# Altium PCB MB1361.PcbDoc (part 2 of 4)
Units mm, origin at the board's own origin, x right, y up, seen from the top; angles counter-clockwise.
Board outline 70 x 133.34 mm, 6 copper layers (Top Layer, Signal Layer 1, Signal Layer 2, Signal Layer 3, Signal Layer 4, Bottom Layer), stack 1.578 mm thick; 268 components, 251 nets, 1066 pads, 705 vias.
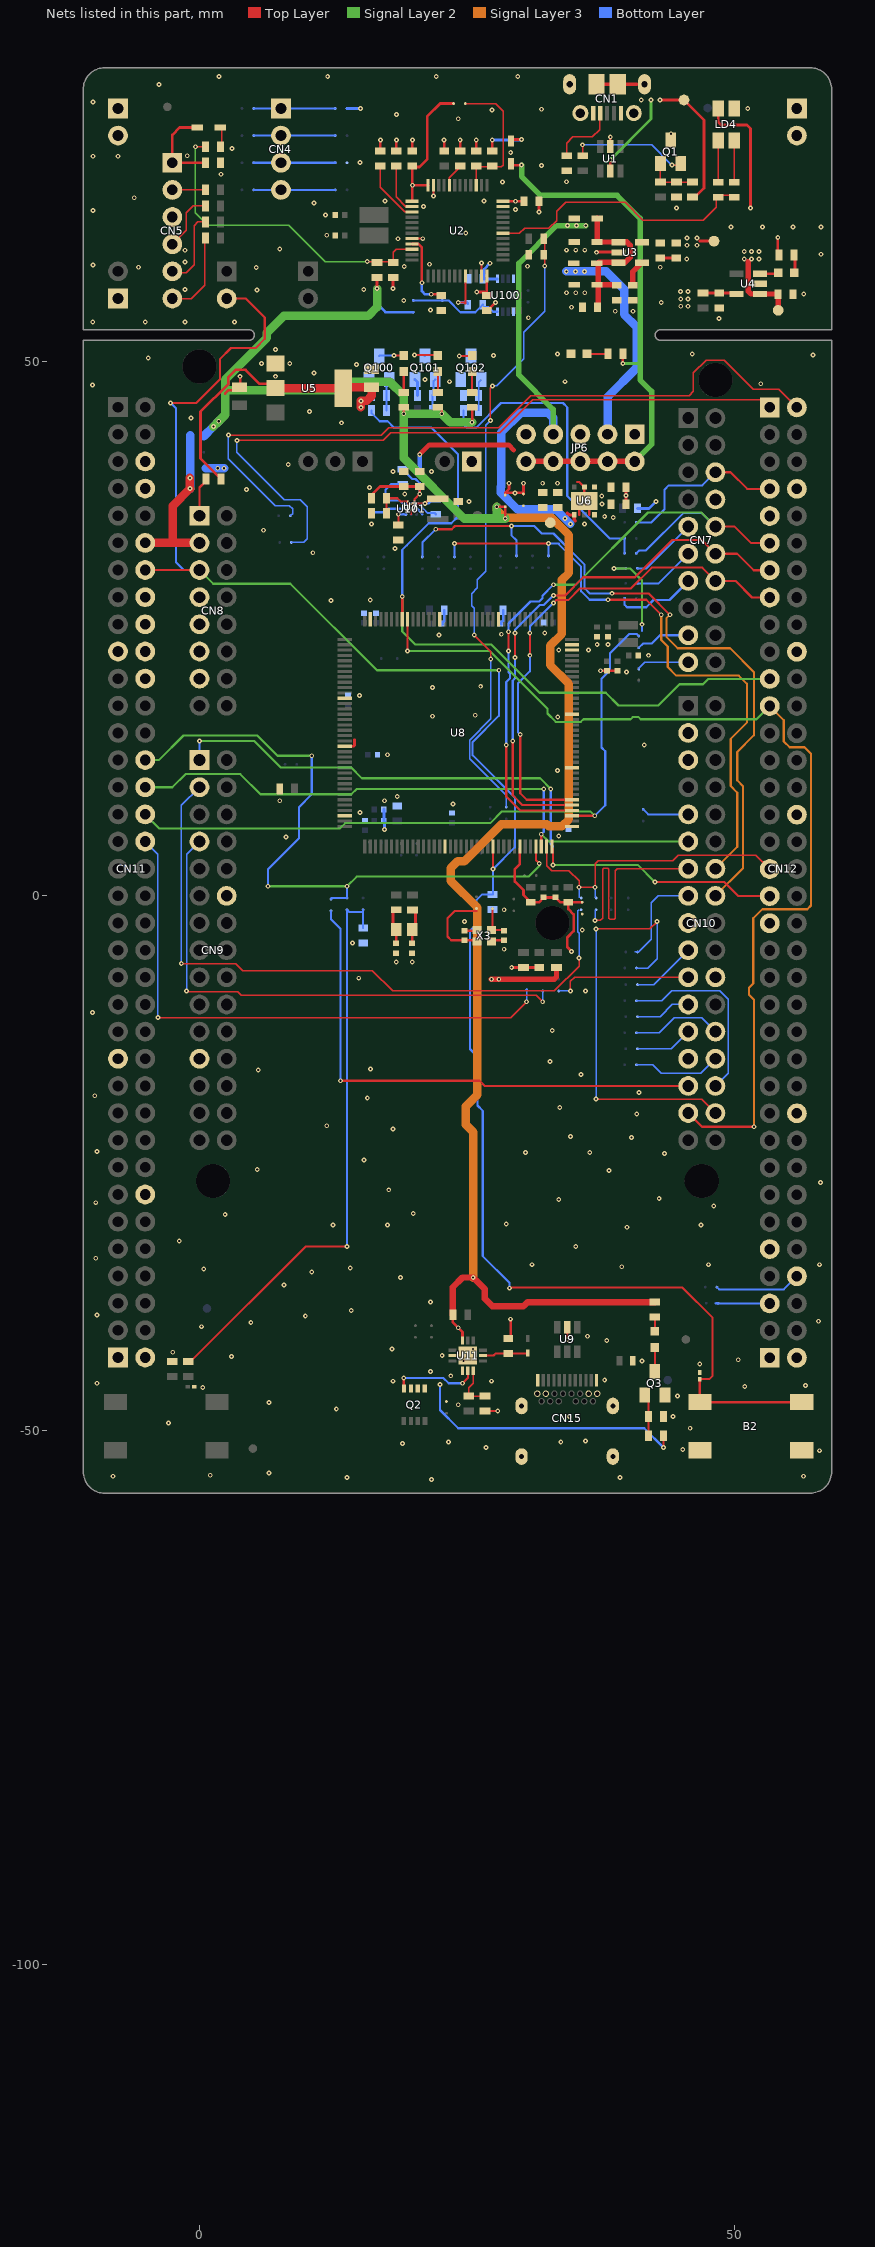
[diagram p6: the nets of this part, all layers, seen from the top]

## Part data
B1: library part MCD-00002, "Non-Open Push-Button 0.1A 24V BLUE", Manufacturer=WEALTHMETAL, Manufacturer_Part_Number=TD0341X-G01-BLU
B2: library part MCD-00001, "Non-Open Push-Button 0.1A 24V BLACK", Manufacturer=WEALTHMETAL, Manufacturer_Part_Number=TD0341X-G01-BLA
C1 C2 C3 C6 C11 C13 C14 C15 C18 C21 C24 C100 C101 C102 C120 C121: library part MCD-00211, "Capacitor, MLCC, 100nF, 16V, X7R, 10%, 0603, T=0,8mm", Manufacturer=YAGEO, Manufacturer_Part_Number=CC0603KRX7R7BB104, Package=C0603
C4 C5: library part MCD-00015, "Capacitor, MLCC, 10pF, 50V, NPO, 5%, 0402, T=0,5mm", Manufacturer=YAGEO, Manufacturer_Part_Number=CC0402JRNPO9BN100, Package=C0402
C7 C9 C12 C20 C22 C30 C31 C114: library part MCD-00010, "Capacitor, MLCC, 1uF, 16V, X5R, 10%, 0603, T=0,8mm", Manufacturer=YAGEO, Manufacturer_Part_Number=CC0603KRX5R7BB105, Package=C0603
C8: library part MCD-00638, "Capacitor, MLCC, 20pF, 50V, NPO, 5%, 0603, T=0,8mm", Manufacturer=YAGEO, Manufacturer_Part_Number=CC0603JRNPO9BN200, Package=C0603
C10: library part MCD-00017, "Capacitor, MLCC, 10nF, 50V, X7R, 10%, 0603, T=0.8mm", Manufacturer=YAGEO, Manufacturer_Part_Number=CC0603KRX7R9BB103, Package=C0603
C16 C17: library part MCD-00014, "Capacitor, MLCC, 10uF, 25V, X5R, 10%, 0805, T=0,85mm", Manufacturer=YAGEO, Manufacturer_Part_Number=CC0805KRX5R8BB106, Package=C0805
C19 C23: library part MCD-00243, "Capacitor, MLCC, 10uF, 6V3, X5R, 10%, 0603, T=0,8mm", Manufacturer=YAGEO, Manufacturer_Part_Number=CC0603KRX5R5BB106, Package=C0603
C25 C32 C33 C105 C106 C107 C108 C109 C110 C111 C112 C113 C116 C117 C118 C119: library part MCD-00102, "Capacitor, MLCC, 100nF, 16V, X7R, 10%, 0402, T=0,5mm", Alternate_Manufacturer=MURATA, Alternate_Manufacturer_Part_Number=GCM155R71C104KA55D, Manufacturer=YAGEO, Manufacturer_Part_Number=CC0402KRX7R7BB104, Package=C0402
C26 C115: library part MCD-01356, "Capacitor, MLCC, 4.7uF, 6V3, X5R, 20%, 0402, T=0,5mm", Manufacturer=MURATA, Manufacturer_Part_Number=GRM155R60J475ME47, Package=C0402
C27: library part MCD-00205, "Capacitor, MLCC, 100pF, 50V, NPO, 5%, 0402, T=0,5mm", Manufacturer=YAGEO, Manufacturer_Part_Number=CC0402JRNPO9BN101, Package=C0402
C28 C29: library part MCD-01355, "Capacitor, MLCC, 10uF, 4V, X5R, 20%, 0402, T=0,5mm", Manufacturer=MURATA, Manufacturer_Part_Number=GRM155R60G106ME44, Package=C0402
C34 C35: library part MCD-00674, "Capacitor, MLCC, 6.8pF, 50V, NPO, +-0.25pF, 0402, T=0.5mm", Manufacturer=YAGEO, Manufacturer_Part_Number=CC0402CRNPO9BN6R8, Package=C0402
C36 C37: library part MCD-00556, "Capacitor, MLCC, 3.9pF, 50V, NPO, +-0.25pF, 0402, T=0,5mm", Manufacturer=YAGEO, Manufacturer_Part_Number=CC0402CRNPO9BN3R9, Package=C0402
C38: library part MCD-00637, "Capacitor, MLCC, 10pF, 50V, NPO, 5%, 0603, T=0,8mm", Manufacturer=YAGEO, Manufacturer_Part_Number=CC0603JRNPO9BN100, Package=C0603
C40: library part MCD-01099, "Capacitor,100nF,50V,X7R,10%,0603", Manufacturer=YAGEO, Manufacturer_Part_Number=CC0603KRX7R9BB104, Package=C0603
C103 C104: library part MCD-01121, "Capacitor, MLCC, 4.7µF, 10V, X5R, 20%, 0603, T=0,8mm", Manufacturer=MURATA, Manufacturer_Part_Number=GRM188R61A475ME15, Package=C0603
CN1: library part MCD-00028, "USB-MICRO-B, 0.65mm, RA, SMT, Bottom Mount,", Manufacturer=MOLEX, Manufacturer_Part_Number=1050170001
CN2 CN3 CN13 CN14: library part MCD-00214, "Header, 2x1, 2,54mm, VR, TH, Height 5.84mm/10.16mm", Manufacturer=SAMTEC, Manufacturer_Part_Number=TSW-102-09-x-S
CN4: library part MCD-00029, "Header, 4x1, 2,54mm, VR, TH, Height 5.84mm/2.54mm", Manufacturer=SAMTEC, Manufacturer_Part_Number=TSW-104-07-x-S
CN5: library part MCD-00212, "Header, 6x1, 2,54mm, VR, TH, Height 5.84mm/2.54mm", Manufacturer=SAMTEC, Manufacturer_Part_Number=TSW-106-07-x-S
CN6: library part MCD-00032, "Header, 2x1, 2,54mm, VR, TH, Height 5.84mm/2.54mm", Manufacturer=SAMTEC, Manufacturer_Part_Number=TSW-102-07-x-S
CN7: library part MCD-01039, "Socket, 10x2, 2.54mm, VR, TH, Height 8.51mm/10mm, Low insertion force.", Manufacturer=SAMTEC, Manufacturer_Part_Number=SSW-110-23-x-D
CN8: library part MCD-01037, "Socket, 8x2, 2.54mm, VR, TH, Height 8.51mm/10mm, Low insertion force.", Manufacturer=SAMTEC, Manufacturer_Part_Number=SSW-108-23-x-D
CN9: library part MCD-01040, "Socket, 15x2, 2.54mm, VR, TH, Height 8.51mm/10mm, Low insertion force.", Manufacturer=SAMTEC, Manufacturer_Part_Number=SSW-115-23-x-D
CN10: library part MCD-01041, "Socket, 17x2, 2.54mm, VR, TH, Height 8.51mm/10mm, Low insertion force", Manufacturer=SAMTEC, Manufacturer_Part_Number=SSW-117-23-x-D
CN11 CN12: library part MCD-01210, "Header, 35x2, 2,54mm, VR, TH, Height 5.84mm/2.54mm", Manufacturer=SAMTEC, Manufacturer_Part_Number=TSW-135-07-x-D
CN15: library part MCD-01108, "USB tyce C certified receptacle for 1.6mm pcb height", Manufacturer="CHANT SINCERE (COXOC)", Manufacturer_Part_Number=317JD24BZTF3K3C3
D1 D2 D3 D4 D5 D6: library part MCD-00034, "BAT60JFILM", Manufacturer=STMICROELECTRONICS
D7: library part MCD-01677, "Small signal Schottky diodes", Manufacturer=STMICROELECTRONICS, Manufacturer_Part_Number=BAT54KFILM, Package=SOD-523
HW101: library part MCD-00235, "Sticker to mention board reference + serial number", Manufacturer=n/a
HW102: library part MCD-00547, "Sticker to mention board CPN code", Manufacturer=n/a
JP2: library part MCD-00045, "Header, 2x1, 2,54mm, VR, TH, Height 5.84mm/2.54mm", Manufacturer=SAMTEC, Manufacturer_Part_Number=TSW-102-07-x-S
JP3 JP5: library part MCD-00683, "Header, 2x1, 2,54mm, VR, TH, Height 5.84mm/2.54mm - Shunt Fitted by default", Manufacturer=SAMTEC, Manufacturer_Part_Number=TSW-102-07-x-S
JP4: library part MCD-00684, "Header, 3x1, 2,54mm, VR, TH, Height 5.84mm/2.54mm - Shunt Fitted 1-2 by default", Manufacturer=SAMTEC, Manufacturer_Part_Number=TSW-103-07-F-S
JP6: library part MCD-01203, "Header, 5x2, 2,54mm, VR, TH, Height 5.84mm/2.54mm - Shunt Fitted 1-2", Manufacturer=SAMTEC, Manufacturer_Part_Number=TSW-105-07-x-D
L1: library part MCD-00240, "FIXED IND 2.2UH 2.6A 100 mOHM 20% SMD", Manufacturer=TDK, Manufacturer_Part_Number=VLS252010HBX-2R2M-1
L2: library part MCD-01786, "Power Inductor 4.7uH 1.1A 160 mOHM 20% SMD Multilayer ferrite.", Manufacturer=TDK, Manufacturer_Part_Number=MLP2016H4R7MT0S1, Package=L0806
LD1 LD6 LD7: library part MCD-00050, "LED, Green, 0603", Manufacturer=EVERLIGHT, Manufacturer_Part_Number=19-213SYGC/S530-E2/TR8, Package="LED 0603"
LD2: library part MCD-00584, "LED Blue, 0603 SMD, 3.3 V Forward Voltage", Manufacturer=VISHAY, Manufacturer_Part_Number=VLMB1300-GS08, Package="LED 0603"
LD3 LD5: library part MCD-00322, "LED, Red, 0603", Manufacturer=EVERLIGHT, Manufacturer_Part_Number=19-217/R6C-AL1M2VY/3T, Package="LED 0603"
LD4: library part MCD-00051, "LED Bicolor", Alternate_Manufacturer=EVERLUCK, Alternate_Manufacturer_Part_Number=LE-RGW35280, Manufacturer="AVAGO TECHNOLOGIES", Manufacturer_Part_Number=HSMF-A201-A00J1
Q1 Q3 Q100 Q101 Q102: library part MCD-00073, "NPN Bipolar Transistor", Manufacturer=NXP, Manufacturer_Part_Number=BSR14
Q2: library part MCD-01810, "N-channel 30 V, 6 mO typ, 11 A STripFET™ H6, Power MOSFET in a PowerFLAT™ 3.3x3.3 package", Manufacturer=STMICROELECTRONICS, Package="PowerFLAT 3.3x3.3"
R1 R10 R19 R24: library part MCD-00224, "Resistor,100R,0603,1%,1/10W", Manufacturer=YAGEO, Manufacturer_Part_Number=RC0603FR-07100RL, Package=R0603
R2 R3 R9 R12 R23 R33 R43 R44: library part MCD-00220, "Resistor,10K,0603,1%,1/10W", Manufacturer=YAGEO, Manufacturer_Part_Number=RC0603FR-0710KL, Package=R0603
R4 R7 R39 R104 R106 R108: library part MCD-00223, "Resistor,100K,0603,1%,1/10W", Manufacturer=YAGEO, Manufacturer_Part_Number=RC0603FR-07100KL, Package=R0603
R5 R21 R22: library part MCD-00219, "Resistor,4K7,0603,1%,1/10W", Manufacturer=YAGEO, Manufacturer_Part_Number=RC0603FR-074K7L, Package=R0603
R6 R45: library part MCD-00218, "Resistor,2K7,0603,1%,1/10W", Manufacturer=YAGEO, Manufacturer_Part_Number=RC0603FR-072K7L, Package=R0603
R8: library part MCD-00217, "Resistor,1K5,0603,1%,1/10W", Manufacturer=YAGEO, Manufacturer_Part_Number=RC0603FR-071K5L, Package=R0603
R11: library part MCD-00221, "Resistor,36K,0603,1%,1/10W", Manufacturer=YAGEO, Manufacturer_Part_Number=RC0603FR-0736KL, Package=R0603
R13 R14 R40: library part MCD-00197, "Resistor,330R,0603,1%,1/10W", Manufacturer=YAGEO, Manufacturer_Part_Number=RC0603FR-07330RL, Package=R0603
R15 R16 R17 R18: library part MCD-00190, "Resistor,22R,0603,1%,1/10W", Manufacturer=YAGEO, Manufacturer_Part_Number=RC0603FR-0722RL, Package=R0603
R20 R25 R28 R31: library part MCD-00070, "Resistor,1K,0603,1%,1/10W", Manufacturer=YAGEO, Manufacturer_Part_Number=RC0603FR-071KL, Package=R0603
R29: library part MCD-00508, "Resistor,680R,0603,1%,1/10W", Manufacturer=YAGEO, Manufacturer_Part_Number=RC0603FR-07680RL, Package=R0603
R30 R38: library part MCD-00225, "Resistor,510R,0603,1%,1/10W", Manufacturer=YAGEO, Manufacturer_Part_Number=RC0603FR-07510RL, Package=R0603
R32: library part MCD-00242, "Resistor,19K6,0603,1%,1/10W", Manufacturer=YAGEO, Manufacturer_Part_Number=RC0603FR-0719K6L, Package=R0603
R34 R35 R100 R101 R102 R103: library part MCD-00056, "Resistor,0R,0603,5%,1/10W", Manufacturer=YAGEO, Manufacturer_Part_Number=RC0603JR-070RL, Package=R0603
R36: library part MCD-01171, "Resistor,49K9,0603,1%", Manufacturer=YAGEO, Manufacturer_Part_Number=RC0603FR-0749K9L, Package=R0603
R37: library part MCD-00458, "Resistor,330K,0603,1%,1/10W", Manufacturer=YAGEO, Manufacturer_Part_Number=RC0603FR-07330KL, Package=R0603
R41: library part MCD-00430, "Resistor,22K,0603,1%,1/10W", Manufacturer=YAGEO, Manufacturer_Part_Number=RC0603FR-0722KL, Package=R0603
R42 R105 R107 R109: library part MCD-00222, "Resistor,47K,0603,1%,1/10W", Manufacturer=YAGEO, Manufacturer_Part_Number=RC0603FR-0747KL, Package=R0603
SB1 SB2 SB3 SB4 SB5 SB6 SB7 SB8 SB9 SB10 SB11 SB12 SB100 SB101 SB102 SB103 SB104 SB105 SB106 SB107 SB108 SB109 SB110 SB111 SB112 SB113 SB114 SB115 SB116 SB117 SB118 SB119 SB120 SB121 SB122 SB123 SB124 SB125 SB126 SB127 SB128 SB129 SB130 SB132 SB133 SB134 SB135 SB136 SB137 SB138 SB139 SB140 SB142 SB143 SB144 SB145 SB146 SB147 SB148 SB149 SB150 SB151 SB152 SB153 SB154 SB155 SB156 SB157 SB158 SB159 SB160 SB161 SB162 SB163 SB164 SB165 SB166 SB167 SB168: library part MCD-00071, "Solder Bridge ON"
TP1 TP2 TP3 TP4 TP5: library part MCD-00074, "Test Point 1mm", Manufacturer=n/a
U1: library part MCD-00163, "Very low capacitance ESD protection", Manufacturer=STMICROELECTRONICS, Manufacturer_Part_Number=USBLC6-2SC6
U2: library part MCD-00085, "Medium-density performance line ARM-based 32-bit MCU with 128KB Flash", Manufacturer=STMICROELECTRONICS, Manufacturer_Part_Number=STM32F103CBT6
U3: library part MCD-00086, "Ultra low drop-low noise BiCMOS voltage, regulators low ESR capacitors compatible", Manufacturer=STMICROELECTRONICS, Manufacturer_Part_Number=LD3985M33R
U4: library part MCD-01785, "5V Power Switch, 0.85A, RDSon 130mOhm max, with active low enable pin", Manufacturer="TEXAS INSTRUMENTS", Manufacturer_Part_Number=TPS2041CDBVT, Package=SOT23_5p
U5: library part MCD-00088, "IC REG LDO 5V 0.8A SOT223", Manufacturer=STMICROELECTRONICS, Manufacturer_Part_Number=LD1117S50TR, Package=SOT-223
U6: library part MCD-00215, "Low quiescent current and low noise voltage regulators", Manufacturer=STMICROELECTRONICS, Manufacturer_Part_Number=LD39050PU33R, Package="DFN6 3x3mm"
U7: library part MCD-00228, "400mA Nano-Quiescent Step down converter", Manufacturer=STMICROELECTRONICS, Manufacturer_Part_Number=ST1PS01EJR
U8: library part MCD-01055, "STM32L552ZET6Q MCU,LQFP144 20x20, 0.5, no AES, Q for Int SMPS", Manufacturer=STMICROELECTRONICS, Package=LQFP144
U9: library part MCD-00163, "Very low capacitance ESD protection", Manufacturer=STMICROELECTRONICS
U10: library part MCD-01207, "High power Transient voltage suppressor:25V/35A EOS and ESD transients protection.", Manufacturer=STMICROELECTRONICS, Manufacturer_Part_Number=ESDA25P35-1U1M, Package=QFN1610
U11: library part MCD-01809, "USB Type-C Port Protection for USB Power Delivery, PPS compliant", Manufacturer=STMICROELECTRONICS, Package=QFN-12L
U12 U13: library part MCD-00170, "ESD protection 6V1", Manufacturer=STMICROELECTRONICS, Manufacturer_Part_Number=ESDALC6V1-1U2
U100: library part MCD-00264, "Dual bit dual supply bus transceiver", Manufacturer="TEXAS INSTRUMENTS", Manufacturer_Part_Number=SN74LVC2T45DCUT
U101: library part MCD-00226, "UL Step down regulator: Opt0", Manufacturer="ANALOG DEVICES", Manufacturer_Part_Number=ADP5301ACBZ-2-R7
X1: library part MCD-00092, "Crystal 8Mhz, 8pF, -+50PPM, SMD", Manufacturer=NDK, Manufacturer_Part_Number="NX3225GD 8MHz EXS00A-CG04874"
X2: library part MCD-01479, "Crystal 32.768kHz, 6pF, -+20PPM, R=80K, SMD", Manufacturer=NDK, Manufacturer_Part_Number="NX2012SA 32.768KHz EXS00A-MU00527", Package=NX2012SA
X3: library part MCD-01476, "Crystal 16 MHz, 8pF, -+20 PPM, R=200O, SMD", Manufacturer=NDK, Manufacturer_Part_Number="NX2016SA 16 MHz EXS00A-CS07826", Package=NX2016SA

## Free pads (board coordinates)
  round 3.2 hole 3.2 unplated: 0(0,49.53) 0(1.27,-26.67) 0(33.02,-2.54) 0(46.99,-26.67) 0(48.26,48.26)
  round 0.508 on Mech16: 1(-0.247,-120.498) 1(48.601,-120.498)

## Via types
v1: diameter 0.45, hole 0.2, Top Layer to Bottom Layer, tented both sides, 705 vias

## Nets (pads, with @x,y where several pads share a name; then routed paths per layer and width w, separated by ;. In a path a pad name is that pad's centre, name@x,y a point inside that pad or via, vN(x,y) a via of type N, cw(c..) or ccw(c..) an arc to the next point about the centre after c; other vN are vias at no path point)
3V3: CN8.7 CN11.16 JP5.1 SB2.1 SB3.2 SB113.1 | length 5.7
  Top Layer w0.25: SB2.1@28.6,37.5 28.6,37.7 ; v1(28.959,38.6) 28.959,38.059 28.6,37.7 ; v1(30.3,38.6) SB3.2@30.3,37.6 30.2,37.7 v1(29.5,37.7) 28.6,37.7
  Bottom Layer w0.8: 0.6,40 v1(1.7,40) v1(2.3,40)
3V3_PER: R21.1 R28.1 R29.1 R30.2 R38.1 R43.2 SB2.2 SB110.2 SB111.1 U11.12 | length 195.5
  Top Layer w0.25: v1(19.1,45.1) R28.1@19.1,45.7 ; R29.1@22.3,45.7 22.632,45.7 22.659,45.673 v1(22.659,45.1) ; R43.2@23.7,-39.2 23.7,-39.9 v1(24.2,-40.4) 24.6,-40.8 U11.12@24.6,-41.575 ; v1(25.5,44.3) R30.2@25.5,45.7 ; v1(27.8,36.4) SB2.2@28.6,36.4 v1(28.6,35.3)
  Top Layer w0.254: v1(16.612,56.812) R21.1@16.612,57.739
  Top Layer w0.6: R43.2@23.7,-39.2 23.7,-36.6 24.6,-35.7 v1(25.6,-35.7) 26.7,-36.8 26.7,-37.7 27.4,-38.4 30.3,-38.4 30.7,-38 R38.1@42.6,-38
  Signal Layer 2 w0.8: v1(1.3,43.9) v1(1.8,44.4) 2.4,45 2.4,47.3 ; v1@16.612,56.769 16.612,55.08 15.786,54.254 7.875,54.254 6.3,52.679 6.3,52.2 2.4,48.3 2.4,47.3 ; v1(25.5,44.3) 23.459,44.3 v1(22.659,45.1) v1(19.1,45.1) ; v1(27.8,36.4) 27.8,35.3 ; v1(28.6,35.3) 27.8,35.3 ; 2.4,47.3 12.7,47.3 13.5,48.1 17.8,48.1 19.1,46.8 v1(19.1,45.1) ; v1(19.1,45.1) 19.1,40.95 24.75,35.3 27.8,35.3
  Signal Layer 3 w0.8: v1(25.6,-35.7) 25.6,-22.1 24.9,-21.4 24.9,-19.7 26,-18.6 26,-1.1 23.5,1.4 23.5,2.6 24.14,3.24 24.778,3.24 28.238,6.7 32.5,6.7 32.695,6.505 33.905,6.505 34.552,7.152 34.552,19.848 32.8,21.6 32.8,23.4 33.9,24.5 33.9,29.563 34.552,30.215 34.552,33.748 32.946,35.354 28.654,35.354 v1(28.6,35.3) 27.8,36.1 v1(27.8,36.4)
  Bottom Layer w0.254: v1@16.6,56.8 16.6,55.4 17.4,54.6 SB110.2@20,54.6
  Bottom Layer w0.8: SB111.1@0.4,43 v1(1.3,43.9) v1(1.8,44.4)
3V3_STLK: C1.2 C3.2 C6.2 C7.2 C13.2 C14.2 C100.2 LD4.4 Q1.3 SB1.1 SB100.2 TP2.1 U2.1 U2.9 U2.24 U2.36 U2.48 U3.5 U100.1 | length 44.4
  Top Layer w0.25: U2.9@19.88,60.98 20.483,60.98 20.581,60.882 20.584,60.882 20.732,60.734 20.732,60.731 20.803,60.66 v1(20.803,57.353)
  Top Layer w0.254: U2.1@19.914,65.012 v1(19.914,66.479) ; U2.48@21.38,66.48 v1(19.914,66.479) v1(19.914,66.479) ; v1(21.679,56.274) C13.2@22.606,56.274 ; SB1.1@23.765,74.117 22.517,74.117 21.3,72.9 21.3,68.9 20.585,68.185 19.914,68.185 v1(19.914,66.479) ; v1(25.933,56.49) 26.657,56.49 C14.2@26.873,56.274 ; C14.2@26.88,56.279 U2.24@26.88,57.979 ; U2.36@28.38,64.98 29.566,64.98 30.35,64.98 C3.2@30.355,64.98 ; v1@29.725,64.973 30.348,64.973 C3.2@30.35,64.975 C3.2@30.355,64.98 ; C3.2@30.522,65.147 C3.2@30.355,64.98 ; Q1.3@44.094,70.367 44.094,70.688 v1(44.094,71.295) ; 46.799,61.25 TP2.1@48.125,61.25 ; LD4.4@48.526,73.661 48.526,72.378 48.793,72.111 51.206,72.111 51.537,71.78 v1(51.537,64.338)
  Bottom Layer w0.25: v1(20.803,57.353) 20.803,56.578 21.107,56.274 v1(21.679,56.274) ; v1(27.178,59.182) 26.606,58.61 26.606,57.709 U100.1@27.844,57.709
  Bottom Layer w0.254: SB100.2@13.8,73.66 v1(15.061,73.66)
  other v1: 45.593,60.858 46.533,60.858 45.593,61.544 46.533,61.544 29.566,64.973
5V: C20.2 C24.2 CN8.9 CN11.18 D2.1 JP6.2 JP6.4 JP6.6 JP6.8 JP6.10 R25.2 SB114.1 U6.1 U6.6 | length 62.3
  Top Layer w0.25: v1(39.6,49.8) R25.2@39.6,50.7
  Top Layer w0.254: D2.1@29.134,68.345 v1@30.115,68.345
  Top Layer w0.45: v1(20.6,41.3) 21.49,42.19 28.91,42.19 29.4,41.7
  Top Layer w0.5: JP6.10@30.55,40.64 JP6.8@33.09,40.64 JP6.6@35.63,40.64 JP6.4@38.17,40.64 JP6.2@40.71,40.64
  Signal Layer 2 w0.25: v1(39.6,49.8) 41.224,49.8 41.3,49.8
  Signal Layer 2 w0.5: v1(30.134,68.364) 30.134,67.301 31.902,65.532 39.065,65.532 41.224,63.373 41.224,49.8 41.224,48.276 42.3,47.2 42.3,42.23 JP6.2@40.71,40.64
  Bottom Layer w0.45: SB114.1@20.6,39.7 v1(20.6,41.3)
  other v1: 38.7,35.4 37.9,35.5 37.645,36.664 37.63,37.413
5V_EXT: CN11.6 D4.1 JP6.5
  other v1: 34.341,60.401 35.192,60.401 36.043,60.401
5V_SMPS_IN: C18.2 C19.2 R100.1 R101.2 SB114.2 U7.A3 U7.B2 | length 10.3
  Top Layer w0.2: R101.2@16.1,37.5 R101.2@16.1,37.2 R101.2@16.32,37.42 ; U7.B2@19.812,36.65 19.874,36.65 U7.A3@20.124,36.9 20.124,37.124 v1(20.6,37.6)
  Top Layer w0.25: R101.2@16.1,37.5 16.9,38.3 C18.2@19.1,38.3 C19.2@20.6,38.3 v1(20.6,37.6)
  Bottom Layer w0.2: R100.1@19,39.9 19.9,39 20.2,39 SB114.2@20.6,38.6
  Bottom Layer w0.25: v1(20.6,37.6) 20.6,38.35
5V_STLK: C11.2 CN12.8 JP6.1 TP3.1 U4.1 | length 7.2
  Top Layer w0.508: 51.35,59.328 51.35,56.55 51.6,56.3 U4.1@52.425,56.3 C11.2@54.125,56.3 TP3.1@54.125,54.775
  other v1: 50.952,59.588 51.638,59.588 52.324,59.588 50.952,60.274 51.638,60.274 52.324,60.274
5V_UCPD: D3.1 JP6.7 Q2.1 Q2.2 Q2.3 R37.2 R42.1 SB12.1 U11.4 | length 78.7
  Top Layer w0.2: v1(43.4,-51.6) R42.1@43.4,-50.5
  Top Layer w0.5: v1(27.3,-7.8) v1(28,-7.8) 33.2,-7.8 33.4,-7.6 R37.2@33.4,-6.7
  Signal Layer 2 w0.508: JP6.7@33.09,43.18 33.09,45.51 29.876,48.724 29.876,59.176 33.4,62.7 v1(34.425,62.7) v1(35.276,62.7) v1(36.127,62.7)
  Bottom Layer w0.2: v1(22.5,-45.7) 22.5,-48.1 24.2,-49.8 41.6,-49.8 v1(43.4,-51.6)
  Bottom Layer w0.8: JP6.7@33.09,43.18 33.09,44.71 32.6,45.2 30.05,45.2 28.207,43.357 28.207,38.289 28.2,38.282 28.2,37.7 29.76,36.14 33.36,36.14 v1(34.2,35.3) v1(34.7,34.8)
  other v1: 23.5,-44.9
5V_USB_STLK: C12.2 CN1.1 D6.1 JP6.9 R12.1 R20.1 R23.1 TP1.1 U1.5 U4.5 | length 26.2
  Top Layer w0.25: TP1.1@45.325,74.45 47.2,72.575 47.2,66.2 46.365,65.365 R12.1@46.119,65.365
  Top Layer w0.254: U1.5@38.43,67.736 U1.5@38.43,67.793 v1(38.43,68.859) ; v1(43.078,74.447) TP1.1@45.322,74.447 ; R23.1@47.1,56.4 C12.2@48.6,56.4 50.125,56.4 U4.5@50.225,56.3 ; v1(54.1,61.6) R20.1@54.1,60.059 ; R20.1@54.115,59.944 R20.1@54.115,60.002 ; R20.1@54.1,60.059 ccw(c54.215,60.059) R20.1@54.115,60.002 ; R20.1@54.1,60.059 ccw(c54.215,60.059) R20.1@54.115,60.002 ; R20.1@54.115,60.002 ccw(c54.215,60.059) R20.1@54.215,59.944 cw(c54.215,60.059) R20.1@54.115,60.002
  Signal Layer 2 w0.254: v1(38.43,68.859) 42.24,72.669 v1(42.24,74.447)
  Bottom Layer w0.254: v1(43.078,74.447) v1@43.078,74.524
  other v1: 45.014,55.15 45.7,55.15 45.014,55.836 45.7,55.836 34.341,56.413 35.192,56.413 36.043,56.413 45.002,56.533 45.702,56.533 41.326,74.447
5V_VIN: C16.2 D5.1 JP6.3 R31.2 U5.2 U5.4 | length 49.7
  Top Layer w0.25: R31.2@2.013,39.013 0.1,40.925 0.1,45.3 2.7,47.9 2.7,48.525 3.375,49.2 4.3,49.2 5.6,47.9 6.71,47.9 U5.2@7.112,47.498
  Top Layer w0.8: U5.2@7.112,47.498 U5.4@13.462,47.498 13.526,47.562 C16.2@16.104,47.562 16.104,46.777 15.627,46.3 15.104,46.3 v1(15.1,46.3) 15.1,45.704 v1(15.104,45.7)
  Bottom Layer w0.8: v1(34.315,58.42) v1(35.166,58.42) v1(36.017,58.42) 38.042,58.42 39.713,56.749 39.713,54.387 40.9,53.2 40.9,49.409 38.17,46.679 JP6.3@38.17,43.18
AGND: C30.2 C31.2 C32.1 C33.1 C102.1 CN10.3 CN12.32 SB9.2 U8.30 | length 18.2
  Top Layer w0.25: U8.30@29.967,4.415 29.967,2.967 29.5,2.5 29.5,1.344 30.303,0.541 30.303,0.097 C31.2@31,-0.6 31.75,-0.6 C32.1@32.2,-0.15 C33.1@33.3,-0.15 33.75,-0.6 C30.2@34.5,-0.6 ; v1(34.8,-5.2) 34.4,-4.8 34.4,-3.9 35,-3.3 35,-1.75 34.5,-1.25 C30.2@34.5,-0.6 ; SB9.2@35.8,-0.6 C30.2@34.5,-0.6
  Bottom Layer w0.25: C102.1@40.967,36.236 42.036,36.236 v1(42.7,36.9)
AIN_1: R1.2 R21.2 R22.2 U2.10 | length 30.2
  Top Layer w0.127: v1(-0.381,70.079) R1.2@0.47,70.079 ; v1(15.687,59.339) 16.612,59.339 18.11,59.339 18.11,60.195 18.403,60.488 19.88,60.488 U2.10@19.88,60.48
  Signal Layer 2 w0.127: v1(-0.381,70.079) -0.381,63.881 0.77,62.73 8.37,62.73 11.761,59.339 v1(15.687,59.339)
ARD_D0_RX: CN10.16 SB125.2 SB130.1 | length 67.5
  Top Layer w0.2: v1(22.1,34.3) 23.6,34.3 23.902,34.602 v1(29.198,34.602) ; v1(38.6,28.3) 42,28.3 v1(44,26.3)
  Signal Layer 3 w0.2: v1(44,26.3) 43.7,26 43.7,24.2 44.741,23.159 49.641,23.159 51.86,20.94 51.86,15.012 50.3,13.452 50.3,10.8 50.848,10.252 50.848,2.588 CN10.16@48.26,0
  Bottom Layer w0.2: SB130.1@20.85,31.7 20.85,33.05 v1(22.1,34.3) ; SB125.2@29.65,31.8 29.65,33.25 29.198,33.702 v1(29.198,34.602) 31.298,34.602 32,33.9 33.112,33.9 36.027,30.985 36.027,28.773 36.51,28.29 36.52,28.3 v1(38.6,28.3)
ARD_D1_TX: CN10.14 SB123.2 SB128.1 | length 58.1
  Top Layer w0.2: v1(23.85,32.95) v1(32.65,32.95) ; v1(38.2,27.7) 41.8,27.7 v1(43.2,26.3)
  Signal Layer 3 w0.2: v1(43.2,26.3) 43.2,23.927 43.8,23.327 43.8,21.406 44.606,20.6 50.448,20.6 51.2,19.848 51.2,16.2 49.69,14.69 49.69,10.27 50.3,9.66 50.3,4.58 CN10.14@48.26,2.54
  Bottom Layer w0.2: SB128.1@23.85,31.7 v1(23.85,32.95) ; SB123.2@32.65,31.8 v1(32.65,32.95) 33.6,32.95 ; 33.6,32.9 35.7,30.8 35.7,28.5 36.5,27.7 v1(38.2,27.7)
GND: B2.3 B2.4 C1.1 C2.1 C3.1 C4.2 C5.2 C6.1 C7.1 C8.2 C9.1 C10.1 C11.1 C12.1 C13.1 C14.1 C15.1 C16.1 C17.1 C18.1 C19.1 C20.1 C21.1 C22.1 C23.1 C24.1 C25.1 C26.1 C27.1 C28.1 C29.1 C34.2 C35.2 C36.2 C37.2 C38.1 C40.1 C100.1 C101.2 C103.1 C104.1 C105.1 C106.1 C107.1 C108.1 C109.1 C110.1 C111.1 C112.1 C113.1 C114.1 C115.1 C116.1 C117.1 C118.1 C119.1 C120.1 C121.1 CN1.5 CN1.6 CN1.7 CN1.8 CN1.9 CN1.10 CN1.11 CN2.1 CN2.2 CN3.1 CN3.2 CN5.3 CN7.8 CN8.11 CN8.13 CN9.12 CN9.23 CN10.5 CN10.17 CN10.22 CN10.27 CN11.8 CN11.19 CN11.20 CN11.22 CN11.49 CN11.60 CN12.9 CN12.20 CN12.39 CN12.54 CN12.63 CN13.1 CN13.2 CN14.1 CN14.2 CN15.A1 CN15.A12 CN15.B1 CN15.B12 CN15.SH1 CN15.SH2 CN15.SH3 CN15.SH4 JP2.1 LD4.1 LD6.2 Q3.2 Q100.2 Q101.2 Q102.2 R2.1 R3.1 R4.1 R5.2 R7.1 R9.2 R11.1 R22.1 R32.2 R33.2 R36.1 R39.1 R41.1 R45.1 R102.2 R104.1 R106.1 R108.1 SB9.1 SB104.2 SB117.1 U1.2 U2.8 U2.20 U2.23 U2.35 U2.47 U3.2 U4.2 U5.1 U6.2 U6.EP U7.D2 U8.16 U8.37 U8.48 U8.58 U8.70 U8.71 U8.83 U8.94 U8.107 U8.120 U8.129 U8.142 U9.2 U10.2 U11.2 U11.13 U12.2 U13.2 U100.4 U100.5 U101.B1 U101.B2 X3.2 X3.4 | length 58.1
  Top Layer w0.127: 19.812,35.63 U7.D2@19.812,36.15
  Top Layer w0.19: R45.1@26.7,-48.2 v1(27.9,-48.2) ; 35.3,38.717 35.517,38.717 35.994,38.24 U6.2@36,38.24
  Top Layer w0.2: v1(34.4,-41.5) U9.2@34.4,-40.35 U9.2@34.4,-40.895
  Top Layer w0.203: U2.8@19.88,61.48 20.882,61.48 v1(20.883,61.479) ; v1(21.88,65.475) U2.47@21.88,66.48 ; v1(24.2,55.5) 24.791,55.5 24.88,55.411 U2.20@24.88,57.98 ; U2.23@26.38,57.98 v1@26.38,59.197
  Top Layer w0.24: 35.526,35.645 U6.EP@35.526,36.535 ; 36.476,35.636 U6.EP@36.476,36.488
  Top Layer w0.25: 2.4,47 2.7,47.3 3.473,47.3 C17.1@3.759,47.586 3.8,47.627 v1(3.8,48.6) ; U8.129@13.392,13.99 U8.129@13.592,13.99 14.39,13.99 14.5,14.1 14.5,14.6 ; U11.2@23.675,-43 U11.13@25.1,-43 ; C34.2@24.8,-3.25 25.95,-3.25 X3.4@26,-3.2 ; X3.2@27.3,-4.2 27.35,-4.15 C35.2@28.5,-4.15 ; C40.1@28.9,-41.4 29.1,-41.2 v1(29.1,-39.6) ; v1(29.2,-6.7) R36.1@30.3,-6.7 C38.1@31.8,-6.7 ; U8.58@35.042,16.99 U8.58@35.082,16.99 ; U6.EP@36,36.94 36,36.964 U6.2@36,38.24 ; v1(37.503,21.06) 38.09,21.06 C28.1@38.1,21.05 C29.1@39.1,21.05 ; C24.1@39.9,36.64 v1(39.9,37.44) C20.1@39.9,38.24 ; C6.1@43.078,59.676 C7.1@44.577,59.676
  Top Layer w0.254: R2.1@16.916,69.786 v1(16.916,70.714) ; v1(18.11,56.812) R22.1@18.11,57.739 ; R3.1@18.415,69.786 v1(18.415,70.714) ; C1.1@19.914,69.786 v1(19.914,70.714) ; C2.1@22.885,69.786 v1(22.885,70.714) ; R4.1@24.384,69.786 v1(24.384,70.714) ; R5.2@25.883,69.786 v1(25.883,70.714) ; C14.1@26.873,54.674 v1(27.7,55.5) ; v1(31.75,63.972) C3.1@31.75,64.975 ; v1@37.135,60.223 U3.2@38.909,60.223 ; U1.2@38.43,70.136 v1(38.43,70.993) ; C12.1@48.475,55 C12.1@48.6,54.875
  Top Layer w0.3: U6.EP@35.526,36.535 U6.EP@35.986,36.995 ; U6.EP@35.98,36.984 36,36.964 U6.EP@36.476,36.488 ; CN1.11@37.03,75.915 37.033,75.918 CN1.11@37.125,75.918 CN1.10@39.125,75.918 40.922,75.918
  Bottom Layer w0.25: Q100.2@15.85,48.3 16.1,48.05 R104.1@16.1,46.8 ; C118.1@17.25,7 C118.1@17.3,6.95 ; U101.B2@19.8,36.2 U101.B1@20.3,36.2 20.377,36.2 20.85,35.727 ; Q101.2@20.15,48.3 20.4,48.05 R106.1@20.4,46.8 ; C109.1@22.734,25.416 C109.1@22.65,25.5 22.9,25.75 C104.1@22.9,26.7 ; v1(24.2,55.5) 25,55.5 C101.2@25.1,55.4 ; C108.1@28.234,25.416 C108.1@28.15,25.5 28.4,25.75 C103.1@28.4,26.7
  Bottom Layer w0.3: C118.1@17.25,7 C115.1@17.25,8.1 ; v1(17.3,6.2) C118.1@17.3,6.95
  other v1: 21.7,-54.6 13.8,-54.4 39.325,-54.4 -8.1,-54.3 56.5,-54.3 1,-54.2 6.5,-54 58,-51.9 45.2,-51.8 26.8,-51.6 19,-51.237 23.3,-51.1 33.8,-51.1 36.1,-51 45.9,-49.8 -2.9,-49.3 34.6,-48.7 44.3,-48.7 12.8,-48 24.2,-47.6 6.5,-47.4 44.7,-46.8 0.3,-46 51,-45.9 56.7,-45.8 -9.6,-45.6 18.1,-45.4 27.3,-45.4 37.9,-45.3 21.6,-44.5 46.8,-43.8 24.7,-43.5 41.4,-43.5 50.4,-43.4 3,-43.1 22.7,-43 -2.5,-42.7 18,-42.4 25.6,-42.4 38.1,-41.6 36.3,-41.2 0.2,-40.3 4.8,-39.9 57.9,-39.8 9.9,-39.3 -9.6,-39.2 14.2,-38.8 21.6,-38 7.9,-36.4 18.8,-35.7 10.5,-35.2 0.4,-34.9 14.1,-34.8 39.5,-34.7 31.1,-34.5 47.6,-34.5 58,-34.5 -9.7,-33.9 35.2,-32.8 -1.9,-32.3 40,-31 12.5,-30.8 17.6,-30.8 46.9,-30.8 28.7,-30.7 2.4,-29.8 20,-29.7 48.1,-29 -9.7,-28.7 33.6,-28.4 43,-28.3 17.7,-27.5 58.1,-26.8 38.3,-25.7 5.4,-25.6 15.4,-24.7 43.5,-24.1 30.5,-24 36.5,-24 -9.6,-23.9 40.4,-22.6 34.7,-22.5 18.1,-21.8 11.9,-21.5 40.9,-20.4 33.7,-19.8 15.7,-18.9 -9.8,-18.7 41.1,-18.4 35.7,-16.7 5.5,-16.3 16,-16.2 32.8,-15.5 33,-12.6 -10,-10.9 36.1,-8.9 14.9,-7.7 18.4,-6.2 19.9,-6.2 28.5,-5 14.3,-4.4 35.8,-3.2 24.8,-2.4 28.5,-1.3 8.1,5.5 33.6,5.6 15,7.8 23.7,8.6 7.5,8.9 17.3,8.9 18.5,9.3 33.492,11.723 17.6,13.2 41.6,14.1 33.517,16.723 21.8,16.8 25.8,16.9 14.957,18.757 21.8,19.5 26.3,19.6 39.931,20.948 42,22.5 33.6,23 36.4,23 37.2,23.5 38.2,23.5 22.4,24.4 28.234,24.475 32.3,24.6 12.3,27.615 15.967,27.667 10.6,32.1 18.3,32.5 6,34.2 16.1,34.8 36,34.8 25.2,36.9 19.2,37.6 4.4,38 15.9,38.2 32.1,38.6 33.5,38.6 18.1,39.7 21.7,39.7 8.3,40.365 13.297,44.25 -0.8,44.7 10.3,45.3 -10,47.8 52.5,47.9 23.4,48.1 34.2,48.1 21.1,48.3 7.1,48.6 10.7,48.9 14.7,49.7 5.8,49.8 8.437,49.8 -4.8,50.3 27.5,50.55 57.4,50.6 33.5,50.7 46.1,50.7 7.1,51.1 -1.372,53.67 -9.982,53.696 -5.08,53.696 3.277,53.696 48.6,54 30.759,54.077 38.887,54.686 40.538,54.686 21.6,54.8 34.798,55.067 43.2,55.5 19.1,55.7 56.528,56.3 5.385,56.667 -1.346,56.717 15.367,56.717 5.309,58.768 -5.7,58.8 43.1,58.8 19.152,58.877 30.696,58.897 -9.957,59.028 21.514,59.08 26.391,59.207 -1.346,59.284 45.58,59.576 58.141,60.02 37.135,60.198 -1.346,60.4 7.5,60.5 18.567,61.468 11.9,61.8 24.9,62 49.716,62.56 52.68,62.56 55.524,62.56 58.141,62.56 11.8,63.7 -9.957,64.108 29.57,64.211 44.62,64.338 20.955,64.491 10.7,64.8 17.348,64.999 26.6,65 -6.1,65.3 28.344,66.777 34.341,66.802 2,67.5 32.004,68.326 15,68.6 -9.957,69.188 -7.62,69.188 -1.145,69.24 29.108,69.545 3.044,69.901 24.2,72.7 18.415,73.1 27.356,73.508 31.979,73.584 51.281,73.661 -9.957,74.27 -3.8,75.9 1.829,76.657 11.989,76.657 22.149,76.657 29.769,76.657
IOREF: CN8.3 CN11.12 SB111.2 SB112.2 SB113.2 | length 16.8
  Top Layer w0.8: CN11.12@-5.08,33.02 -2.5,33.02 ; v1(-0.9,39.1) -0.9,38.119 v1(-0.881,38.1) -2.5,36.481 -2.5,33.02 ; CN8.3@0,33.02 -2.5,33.02
  Bottom Layer w0.8: v1(-0.881,38.1) -0.881,39.1 -0.881,43.074
LED_STLINK: R13.2 R14.2 U2.30 | length 25.7
  Top Layer w0.127: U2.30@28.38,61.98 29.93,61.98 30.409,62.459 32.684,62.459 33.4,63.175 33.4,64.025 34.25,64.875 39.821,64.875 41.475,63.221 47.134,63.221 48.347,64.434 48.347,65.35 48.347,65.54 48.525,65.54 49.738,65.54 49.976,65.302 R14.2@50.013,65.265
MCO: C8.1 R19.2 SB143.2 | length 59.2
  Top Layer w0.127: v1(25.7,24.4) 27.247,22.853 v1(27.247,22.153) ; v1(27.208,44.465) 27.208,47.508 v1(27.4,47.7) ; v1(32.296,58.915) 32.296,59.969 R19.2@32.296,61.468
  Bottom Layer w0.127: v1(25.7,24.4) 25.7,26.9 25.467,27.133 25.467,28.267 26,28.8 26,29.59 26.784,30.374 26.784,44.042 v1(27.208,44.465) ; v1(27.247,22.153) 27.247,16.547 25.257,14.557 25.257,12.843 28.7,9.4 SB143.2@28.7,8.3 ; v1(27.4,47.7) 27.8,47.7 30.323,50.223 30.323,52.7 32.296,54.673 v1(32.296,58.915)
NetC9_2: C9.2 C15.2 D3.2 D4.2 D5.2 D6.2 U3.1 U3.3 | length 15.4
  Top Layer w0.254: D4.2@37.189,61.163 D4.2@37.195,61.169
  Top Layer w0.508: D4.2@37.195,61.169 D3.2@37.195,63.375 ; D5.2@37.293,59.182 37.385,59.273 39.177,59.273 39.842,59.273 40.284,59.715 40.284,60.858 39.969,61.173 39.177,61.173 U3.1@39.109,61.173 ; D5.2@37.319,59.157 D6.2@37.319,57.175 ; D4.2@37.319,61.163 U3.1@39.109,61.163 ; C15.2@37.325,55.067 37.319,55.074 D6.2@37.319,57.175 ; C9.2@39.002,57.175 D6.2@37.319,57.175
NetC10_2: C10.2 U3.4 | length 2.4
  Top Layer w0.508: C10.2@40.538,57.213 40.538,58.403 41.374,59.238 U3.4@41.409,59.273
NetC21_2: C21.2 C22.2 SB3.1 TP5.1 U6.4 | length 1.3
  Top Layer w0.3: 34.408,35.802 34.57,35.64 U6.4@35.05,35.64 35.05,35.168 35.146,35.073
NetC40_2: C40.2 D7.2 U11.8 | length 4.3
  Top Layer w0.2: U11.8@26.525,-43 27.5,-43 27.7,-42.8 C40.2@28.9,-42.8 30.675,-42.8 D7.2@30.7,-42.775
NetC101_1: C101.1 SB109.1 SB110.1 U100.8 | length 8.8
  Bottom Layer w0.2: SB110.1@20,55.7 SB109.1@22.7,55.7 ; SB109.1@22.6,55.7 SB109.1@22.7,55.7 ; C101.1@26.5,55.3 25.8,54.6 24.4,54.6 23.3,55.7 SB109.1@22.7,55.7 ; C101.1@26.6,55.1 27,55.1 27.465,54.635 U100.8@27.876,54.635
NetC121_2: C121.2 R40.1 SB154.1 SB155.1 | length 54.1
  Top Layer w0.2: R40.1@-1.05,-43.55 -0.825,-43.55 9.925,-32.8 v1(13.8,-32.8)
  Bottom Layer w0.2: v1(13.8,-32.8) SB155.1@13.8,-1.3 14,-1.5 15.3,-1.5 ; C121.2@15.3,-3 15.3,-1.5 ; SB154.1@15.3,-1.3 15.3,-1.5
NetCN1_4: CN1.4 R7.2 | length 6.3
  Top Layer w0.127: R7.2@34.341,69.329 34.341,70.407 34.926,70.993 36.754,70.993 37.45,71.689 37.45,73.218 CN1.4@37.45,73.279
NetCN4_1: CN4.1 SB100.1 SB101.2 | length 7.6
  Bottom Layer w0.2: SB101.2@5.07,73.66 7.62,73.66 SB100.1@12.7,73.66
NetCN4_2: CN4.2 SB102.1 SB103.2 | length 7.6
  Bottom Layer w0.2: SB103.2@5.07,71.12 7.619,71.12 CN4.2@7.62,71.121 7.621,71.12 SB102.1@12.7,71.12
NetCN4_3: CN4.3 SB104.1 SB105.2 | length 7.6
  Bottom Layer w0.2: SB105.2@5.07,68.58 7.619,68.58 CN4.3@7.62,68.581 SB104.1@12.7,68.581 ; SB104.1@12.7,68.58 SB104.1@12.701,68.581
NetCN4_4: CN4.4 SB106.1 SB107.2 | length 7.6
  Bottom Layer w0.2: SB107.2@5.07,66.04 7.619,66.04 CN4.4@7.62,66.041 7.621,66.04 SB106.1@12.7,66.04
NetCN5_1: CN5.1 D1.1 R9.1 | length 8.1
  Top Layer w0.127: CN5.1@-2.54,68.58 CN5.1@-2.54,68.58 ; D1.1@-0.336,71.881 D1.1@-0.311,71.881
  Top Layer w0.254: CN5.1@-2.54,68.58 -2.54,71.195 -1.853,71.882 D1.1@-0.336,71.882 ; CN5.1@-2.54,68.58 R9.1@0.47,68.58
NetCN5_2: CN5.2 R15.1 | length 3
  Top Layer w0.127: CN5.2@-2.54,66.04 R15.1@0.432,66.04
NetCN5_4: CN5.4 R16.1 | length 5.4
  Top Layer w0.127: CN5.4@-2.54,60.96 -1.236,62.264 -1.236,63.889 -0.584,64.541 R16.1@0.47,64.541
NetCN5_5: CN5.5 R17.1 | length 7.2
  Top Layer w0.127: CN5.5@-2.54,58.42 -2.426,58.304 -1.245,58.304 -0.508,59.041 -0.508,62.687 -0.152,63.043 R17.1@0.47,63.043
NetCN5_6: CN5.6 R18.1 | length 8
  Top Layer w0.127: CN5.6@-2.54,55.88 -0.762,55.879 0.47,57.111 R18.1@0.47,61.544
NetCN7_6: CN7.6 CN12.7 SB115.1 | length 16.1
  Top Layer w0.2: CN7.6@48.26,39.624 49.676,39.624 51.225,38.075 CN12.7@53.34,38.075
  Bottom Layer w0.2: SB115.1@40.867,34.936 42.277,34.936 43.5,36.159 43.5,38 43.9,38.4 43.901,38.399 47.035,38.399 CN7.6@48.26,39.624
NetCN7_9: CN7.9 SB121.2 | length 6.4
  Bottom Layer w0.2: SB121.2@40.967,30.636 41.812,30.636 CN7.9@45.72,34.544
NetCN7_11: CN7.11 SB134.2 | length 5.9
  Bottom Layer w0.2: SB134.2@40.967,29.236 42.952,29.236 CN7.11@45.72,32.004
NetCN7_13: CN7.13 SB135.2 | length 7.7
  Bottom Layer w0.2: SB135.2@39.767,27.836 39.767,27.22 39.986,27 41.8,27 42.473,27.673 43.973,27.673 CN7.13@45.7,29.4 ; CN7.13@45.7,29.464 CN7.13@45.72,29.464
NetCN7_17: CN7.17 SB136.2 | length 5.1
  Bottom Layer w0.2: SB136.2@41.1,23.2 41.5,23.6 42.3,23.6 43.084,24.384 CN7.17@45.72,24.384
NetCN7_19: CN7.19 SB139.2 | length 4.9
  Bottom Layer w0.127: SB139.2@41.1,21.2 41.1,21.3 41.644,21.844 CN7.19@45.72,21.844
NetCN8_1: CN8.1 R31.1 | length 3.7
  Top Layer w0.2: CN8.1@0,35.56 0,38.2 0.6,38.8 R31.1@0.6,39
NetCN9_3: CN9.3 SB153.2 | length 61.8
  Top Layer w0.127: v1(-1.7,-6.33) 3.375,-6.33 4.045,-7 16.155,-7 18.055,-8.9 33.2,-8.9 35.5,-6.6 v1(35.5,-5.8)
  Bottom Layer w0.127: v1(-1.7,-6.33) -1.7,8.46 CN9.3@0,10.16 ; v1(35.5,-5.8) 35.5,-3.488 35.384,-3.372 35.384,-1.416 35.5,-1.3
NetCN9_7: CN9.7 SB161.2 | length 49.2
  Top Layer w0.127: v1(-1.205,-8.9) -1.133,-8.972 3.572,-8.972 3.9,-9.3 31.501,-9.3 v1(32.1,-9.9)
  Bottom Layer w0.127: v1(-1.205,-8.9) -1.205,3.875 CN9.7@0,5.08 ; v1(32.1,-9.9) SB161.2@32.1,-8.9
NetCN10_9: CN10.9 SB144.2 | length 4.4
  Bottom Layer w0.2: SB144.2@41.5,8.1 41.98,7.62 CN10.9@45.72,7.62
NetCN10_13: CN10.13 SB152.2 | length 23.7
  Top Layer w0.127: v1(37,-2.3) 37.5,-2.3 37.7,-2.1 37.7,2.4 37.7,2.5 37.8,2.6 38.2,2.6 38.3,2.5 38.3,-2.1 38.4,-2.2 38.8,-2.2 38.9,-2.1 38.9,2.34 39.1,2.54 CN10.13@45.72,2.54
  Bottom Layer w0.127: v1(37,-2.3) SB152.2@37,-1.3
NetCN10_15: CN10.15 SB151.2 | length 9.2
  Bottom Layer w0.127: 40.725,-5.25 41.075,-5.25 42.272,-4.053 42.272,-0.628 42.9,0 CN10.15@45.72,0
NetCN10_19: CN10.19 SB158.2 | length 6.1
  Bottom Layer w0.127: SB158.2@40.975,-8.3 42.5,-8.3 CN10.19@45.72,-5.08
NetCN10_21: CN10.21 SB160.2 | length 13.2
  Top Layer w0.127: v1(34.7,-8.9) 34.7,-8 35.08,-7.62 CN10.21@45.72,-7.62
  Bottom Layer w0.127: SB160.2@33.6,-8.9 v1(34.7,-8.9)
NetCN10_23: CN10.23 SB163.2 | length 5.4
  Top Layer w0.127: CN10.23@45.72,-10.37 CN10.23@45.72,-10.16
  Bottom Layer w0.127: SB163.2@40.975,-11.3 43.1,-11.3 44.24,-10.16 CN10.23@45.72,-10.16
NetCN10_25: CN10.25 SB165.2 | length 5.4
  Bottom Layer w0.127: SB165.2@40.975,-14.3 44.12,-14.3 CN10.25@45.72,-12.7
NetCN10_26: CN10.26 SB164.1 | length 8.5
  Bottom Layer w0.127: SB164.1@40.875,-12.8 43,-12.8 44.39,-11.41 46.97,-11.41 CN10.26@48.26,-12.7
NetCN10_28: CN10.28 SB166.1 | length 8.3
  Bottom Layer w0.127: SB166.1@40.875,-15.8 42.4,-15.8 43.192,-16.592 46.908,-16.592 CN10.28@48.26,-15.24
NetCN10_29: CN10.29 SB156.2 | length 49
  Top Layer w0.2: v1(13.2,-17.3) 26.2,-17.3 26.68,-17.78 CN10.29@45.72,-17.78
  Bottom Layer w0.2: SB156.2@12.3,-1.4 12.3,-2.2 13.2,-3.1 v1(13.2,-17.3)
NetCN10_30: CN10.30 SB159.1 | length 17.9
  Bottom Layer w0.127: SB159.1@40.875,-9.8 43.263,-9.8 44.163,-8.9 48.681,-8.9 49.465,-9.684 49.465,-16.575 CN10.30@48.26,-17.78
NetCN10_32: CN10.32 SB157.1 | length 39.4
  Top Layer w0.127: v1(37.1,-19) 37.13,-19.03 46.97,-19.03 CN10.32@48.26,-20.32 ; v1(37.1,-3.1) 42.1,-3.1 v1(42.8,-2.4)
  Bottom Layer w0.127: v1(37.1,-19) v1(37.1,-3.1) ; SB157.1@40.875,-6.75 41.95,-6.75 42.8,-5.9 v1(42.8,-2.4)
NetCN11_34: CN11.34 SB162.1 | length 53.2
  Top Layer w0.127: v1(-3.892,-11.392) 29.108,-11.392 v1(30.6,-9.9)
  Bottom Layer w0.127: CN11.34@-5.08,5.08 -3.892,3.892 v1(-3.892,-11.392) ; v1(30.6,-9.9) SB162.1@30.6,-8.8
NetCN12_1: CN12.1 SB122.2 | length 66.2
  Top Layer w0.127: v1(3.5,42.6) 17.2,42.6 17.9,43.3 28.1,43.3 31.196,46.396 52.639,46.396 CN12.1@53.34,45.695
  Bottom Layer w0.127: v1(3.5,42.6) 3.5,41.5 7.926,37.074 9.426,37.074 10.1,36.4 10.1,33.4 9.76,33.06 SB122.2@8.6,33.06
NetCN12_2: CN12.2 SB119.1 | length 69.8
  Top Layer w0.127: v1(2.7,43.1) 17,43.1 17.7,43.8 28,43.8 31,46.8 45.8,46.8 46.2,47.2 46.2,48.924 47.4,50.124 49.076,50.124 51.8,47.4 54.175,47.4 CN12.2@55.88,45.695
  Bottom Layer w0.127: v1(2.7,43.1) 2.7,40.9 7.1,36.5 8.4,36.5 8.7,36.2 8.7,35.76 SB119.1@8.5,35.56
NetCN12_66: CN12.66 SB167.1 | length 8.1
  Bottom Layer w0.2: SB167.1@48.4,-36.6 48.61,-36.81 54.655,-36.81 CN12.66@55.88,-35.585
NetCN12_67: CN12.67 SB168.2 | length 5.3
  Bottom Layer w0.2: SB168.2@48.5,-38.1 48.3,-38.1 48.275,-38.125 CN12.67@53.34,-38.125
NetD1_2: D1.2 R1.1 | length 1.8
  Top Layer w0.127: D1.2@2.064,71.882 2.07,71.876 R1.1@2.07,70.079
NetD2_2: D2.2 R6.1 | length 4.8
  Top Layer w0.254: R6.1@27.381,69.786 v1(27.381,70.714) ; D2.2@29.134,70.745 v1@30.115,70.745
  Bottom Layer w0.127: v1@30.084,70.814 v1(30.134,70.764)
  Bottom Layer w0.254: v1(27.381,70.714) 30.083,70.714 v1(30.134,70.764)
NetL1_1: L1.1 R103.1 U7.C3 | length 3.7
  Top Layer w0.2: U7.C3@20.124,36.4 20.424,36.7 v1(21.1,36.7) 21.55,37.15 L1.1@22.3,37.15
  Bottom Layer w0.2: v1(21.1,36.7) 21.425,36.7 21.825,37.1 R103.1@22.1,37.1
NetLD1_1: LD1.1 R30.1 | length 1.9
  Top Layer w0.2: R30.1@25.5,47.3 LD1.1@25.5,49.05
  Top Layer w0.25: R30.1@25.5,47.3 R30.1@25.6,47.2
NetLD1_2: LD1.2 Q102.3 | length 2.3
  Top Layer w0.2: v1(24.3,50.5) 25.45,50.5 LD1.2@25.5,50.55
  Bottom Layer w0.2: v1(24.3,50.5) Q102.3@25.4,50.5
NetLD2_1: LD2.1 R29.2 | length 1.9
  Top Layer w0.2: R29.2@22.3,47.3 LD2.1@22.3,49.05
  Top Layer w0.25: R29.2@22.3,47.3 R29.2@22.4,47.2
NetLD2_2: LD2.2 Q101.3 | length 3.3
  Top Layer w0.2: v1(20.1,50.6) 22.25,50.6 LD2.2@22.3,50.55
  Bottom Layer w0.2: v1(20.1,50.6) 21,50.6 Q101.3@21.1,50.5
NetLD3_1: LD3.1 R28.2 | length 2.2
  Top Layer w0.2: R28.2@19.1,47 R28.2@19.1,47.1 LD3.1@19.1,49.05
  Top Layer w0.25: R28.2@19.1,47 R28.2@19.2,46.9
NetLD3_2: LD3.2 Q100.3 | length 2.3
  Top Layer w0.2: v1(18.2,50.55) LD3.2@19.1,50.55
  Bottom Layer w0.2: Q100.3@16.8,50.5 16.85,50.55 v1(18.2,50.55)
NetLD4_2: LD4.2 R14.1 | length 3.9
  Top Layer w0.127: R14.1@50.025,66.75 50.026,66.751 LD4.2@50.026,70.661
NetLD4_3: LD4.3 R13.1 | length 3.8
  Top Layer w0.127: R13.1@48.514,66.865 48.526,66.877 LD4.3@48.526,70.661
NetLD5_1: LD5.1 R20.2 | length 1.7
  Top Layer w0.254: LD5.1@55.715,58.268 55.715,58.275 R20.2@55.715,59.944
NetLD5_2: LD5.2 U4.3 | length 1.7
  Top Layer w0.254: U4.3@52.425,58.2 54.05,58.2 LD5.2@54.125,58.275
NetLD6_1: LD6.1 R25.1 | length 2
  Top Layer w0.2: LD6.1@36.2,50.7 LD6.1@36.25,50.7 R25.1@38.2,50.7
NetLD7_1: LD7.1 R38.2 | length 1.3
  Top Layer w0.2: LD7.1@42.6,-40.75 R38.2@42.6,-39.4
NetLD7_2: LD7.2 Q3.3 | length 2.2
  Top Layer w0.2: Q3.3@42.6,-44.5 LD7.2@42.6,-42.25
NetQ1_1: Q1.1 R10.1 R11.2 R12.2 | length 4.5
  Top Layer w0.127: R10.1@43.122,66.865 Q1.1@43.122,68.36
  Top Layer w0.13: R10.1@43.122,66.765 R11.2@44.62,66.765 R12.2@46.119,66.765
NetQ1_2: Q1.2 R8.1 | length 10.9
  Top Layer w0.127: R8.1@35.839,69.329 v1@35.839,70.18 ; v1(44.194,68.367) 45.019,68.367 Q1.2@45.074,68.367
  Bottom Layer w0.127: v1(35.839,70.256) 42.305,70.256 v1(44.194,68.367)
NetQ2_4: Q2.4 U11.5 | length 8.1
  Top Layer w0.2: Q2.4@19.1,-46.1 19.1,-46.075 v1(19.1,-45.1) ; v1(24.6,-45.6) 25.1,-45.1 U11.5@25.1,-44.425
  Bottom Layer w0.2: v1(19.1,-45.1) 22.8,-45.1 23.3,-45.6 v1(24.6,-45.6)
NetQ3_1: Q3.1 R41.2 R42.2 | length 3.9
  Top Layer w0.2: Q3.1@41.65,-46.7 42,-47.05 R41.2@42,-48.7 R42.2@42,-50.5
NetQ100_1: Q100.1 R104.2 R105.2 | length 3
  Bottom Layer w0.2: R105.2@17.5,45.4 R104.2@17.5,46.8 17.5,48.05 Q100.1@17.75,48.3
NetQ101_1: Q101.1 R106.2 R107.2 | length 3
  Bottom Layer w0.2: R107.2@21.8,45.4 R106.2@21.8,46.8 21.9,46.9 21.9,48.15 Q101.1@22.05,48.3
NetQ102_1: Q102.1 R108.2 R109.2 | length 3
  Bottom Layer w0.127: R109.2@26.1,45.4 R108.2@26.1,46.8 26.1,48.05 Q102.1@26.35,48.3
NetR2_2: R2.2 U2.3 | length 5.8
  Top Layer w0.127: R2.2@16.916,68.186 16.916,66.267 19.204,63.98 U2.3@19.88,63.98
NetR3_2: R3.2 U2.2 | length 4.7
  Top Layer w0.127: R3.2@18.415,68.193 18.415,65.38 19.316,64.479 U2.2@19.88,64.479
NetR4_2: R4.2 U2.44 | length 2.1
  Top Layer w0.127: U2.44@23.38,66.48 U2.44@23.38,66.48 23.38,67.173 R4.2@24.392,68.185
NetR5_1: R5.1 R6.2 SB1.2 U2.39 | length 13.2
  Top Layer w0.127: SB1.2@24.865,74.117 27.711,74.117 28.409,73.42 28.409,68.351 28.244,68.186 R6.2@27.381,68.186 ; U2.39@25.88,66.48 U2.39@25.88,66.48 R5.1@25.88,68.182 ; R5.1@25.883,68.185 R6.2@27.381,68.185
NetR32_1: R32.1 U101.C3 | length 1.7
  Top Layer w0.2: R32.1@18.6,34.7 v1(18.6,35.7)
  Bottom Layer w0.25: v1(18.6,35.7) U101.C3@19.3,35.7
NetR44_1: R44.1 R45.2 U11.6 | length 4
  Top Layer w0.127: U11.6@25.6,-44.425 25.6,-45.6 25.2,-46 R44.1@25.2,-46.8 R45.2@26.7,-46.8
NetR100_2: R100.2 SB116.1 U101.A2 U101.A3 | length 5.3
  Bottom Layer w0.2: R100.2@19,38.5 17.9,38.5 17.4,38 SB116.1@17.4,37 18.7,37 19,36.7 U101.A3@19.3,36.7 U101.A2@19.8,36.7
NetR101_1: R101.1 R102.1 U7.A1 U7.C1 | length 4
  Top Layer w0.15: U7.C1@19.5,36.4 U7.A1@19.5,36.9
  Top Layer w0.2: R102.1@17.5,35.8 R101.1@17.5,37.2 18.5,37.2 18.8,36.9 U7.A1@19.5,36.9
NetR103_2: R103.2 U101.A1 | length 2.2
  Bottom Layer w0.2: U101.A1@20.3,36.7 20.461,36.7 21.361,35.8 22,35.8 R103.2@22.1,35.7
NetR109_1: R109.1 SB118.2 SB120.2 | length 29
  Bottom Layer w0.2: R109.1@24.7,45.4 24.7,44.1 25,43.8 25.9,43.8 28.2,46.1 34,46.1 34.4,45.7 34.4,37.4 38.363,33.436 SB118.2@39.767,33.436 SB120.2@39.767,32.036
NetSB116_2: SB116.2 SB117.2 U101.B3 | length 3.5
  Bottom Layer w0.25: SB117.2@15.9,35.9 SB116.2@17.4,35.9 17.7,36.2 U101.B3@19.3,36.2
NRST: B2.1 B2.2 C120.2 CN8.5 CN11.14 JP3.2 U8.25 U13.1 | length 178.1
  Top Layer w0.2: CN11.14@-5.08,30.48 CN8.5@0,30.48 ; v1(-2.7,46.1) -0.3,46.1 1.9,48.3 1.9,50.2 2.95,51.25 5.25,51.25 6.1,52.1 6.1,54.1 4.321,55.879 JP3.2@2.54,55.879 ; v1(27.467,2.513) U8.25@27.467,4.415 ; v1(29,-36.7) 29.052,-36.648 45.187,-36.648 48,-39.461 48,-44.9 47.688,-45.212 U13.1@46.8,-45.212
  Top Layer w0.25: U13.1@46.8,-45.212 46.8,-47.319 B2.1@46.837,-47.356 B2.2@56.337,-47.356
  Signal Layer 2 w0.2: CN8.5@0,30.48 1.28,29.2 8.5,29.2 16.6,21.1 v1(28,21.1)
  Bottom Layer w0.2: v1(-2.7,46.1) -2.2,45.6 -2.2,31.2 -1.48,30.48 CN8.5@0,30.48 ; v1(28,21.1) 28,16.839 25.548,14.387 25.548,13.152 29.5,9.2 29.5,4.546 v1(27.467,2.513) 27.467,0.173 C120.2@27.409,0.114 26.414,0.114 25.9,-0.4 25.9,-2.688 25.3,-3.288 25.3,-14.327 26,-15.027 26,-19.616 26.5,-20.116 26.5,-33.7 29,-36.2 v1(29,-36.7)
OSC32_IN: C36.1 R34.2 X2.2 | length 3.3
  Top Layer w0.2: C36.1@18.4,-4.45 18.4,-3.154 X2.2@18.404,-3.151
  Top Layer w0.25: X2.2@18.1,-2.954 18.1,-1.304 R34.2@18.417,-1.304
OSC32_OUT: C37.1 R35.2 X2.1 | length 3.2
  Top Layer w0.2: C37.1@19.9,-4.45 19.9,-3.154 X2.1@19.904,-3.151
  Top Layer w0.25: R35.2@19.916,-1.311 20.166,-1.311 20.2,-1.345 X2.1@20.2,-2.947
OSC_IN: C34.1 SB6.2 X3.1 | length 7.8
  Top Layer w0.2: C34.1@24.8,-4.2 24.775,-4.175 24.75,-4.15 23.55,-4.15 23.2,-3.8 23.2,-2.1 23.9,-1.4 25.9,-1.4 ; C34.1@24.8,-4.15 X3.1@25.862,-4.15 ; X3.1@25.972,-4.26 X3.1@25.862,-4.15 ; X3.1@26,-4.2 25.95,-4.15 X3.1@25.862,-4.15
OSC_OUT: C35.1 SB7.2 X3.3 | length 3.1
  Top Layer w0.2: SB7.2@27.409,-1.185 27.409,-3.123 X3.3@27.322,-3.21 28.39,-3.21 C35.1@28.4,-3.2
PA0: CN11.28 SB155.2 SB156.1 U8.33 | length 61.8
  Top Layer w0.2: U8.33@31.467,4.415 31.467,3.347 v1(31.776,3.037)
  Signal Layer 2 w0.2: CN11.28@-5.08,12.7 -3.8,12.7 -1.5,15 5.4,15 7.3,13.1 v1(10.5,13.1) ; v1(6.4,0.9) v1(13.8,0.9) 14.701,1.8 30.779,1.8 31.776,2.798 v1(31.776,3.037)
  Bottom Layer w0.2: v1(6.4,0.9) 6.4,2.5 9.3,5.4 9.3,8.3 10.5,9.5 v1(10.5,13.1) ; SB156.1@12.3,-0.3 12.4,-0.2 SB155.2@13.8,-0.2 v1(13.8,0.9)
PA1: CN10.11 CN11.30 U8.34 | length 58.5
  Top Layer w0.2: U8.34@31.967,4.415 U8.34@31.967,4.615 v1(31.967,5.767)
  Signal Layer 2 w0.2: CN11.30@-5.08,10.16 -2.54,10.16 -1.315,11.385 3.815,11.385 5.7,9.5 14.2,9.5 14.7,10 v1(32.2,10) ; v1(31.967,5.767) 32.654,5.08 CN10.11@45.72,5.08
  Bottom Layer w0.2: v1(31.967,5.767) 32.2,6 v1(32.2,10)
PA2: CN12.35 SB152.1 SB153.1 U8.35 | length 28.7
  Top Layer w0.127: U8.35@32.467,4.415 32.467,2.836 32.95,2.354 34.546,2.354 35.5,1.4 v1(35.5,0.8) v1(37,0.8) 37,3 37.3,3.3 44.275,3.3 44.775,3.8 52.055,3.8 CN12.35@53.34,2.515
  Bottom Layer w0.127: 35.5,-0.2 v1(35.5,0.8) ; SB152.1@37,-0.2 v1(37,0.8)
PA3: CN9.1 CN12.37 U8.36 | length 66.7
  Top Layer w0.2: v1(33.067,2.9) U8.36@33.067,4.415 ; v1(42.6,1.3) 49.1,1.3 50.425,-0.025 CN12.37@53.34,-0.025
  Signal Layer 2 w0.2: v1(0,14.5) 5.1,14.5 7.6,12 14.19,12 15.19,11 31.863,11 v1(32.863,10) ; v1(33.067,2.9) 41,2.9 v1(42.6,1.3)
  Bottom Layer w0.2: CN9.1@0,12.7 v1(0,14.5) ; v1(32.863,10) 32.863,4.837 33.067,4.633 v1(33.067,2.9)
PA4: CN11.32 SB121.1 SB136.1 U8.39 | length 73.9
  Top Layer w0.2: U8.39@35.067,7.49 v1(36.969,7.49)
  Signal Layer 2 w0.2: CN11.32@-5.08,7.62 -3.765,6.305 3.047,6.305 3.052,6.3 13.127,6.3 13.627,6.8 27.2,6.8 28.3,7.9 36.559,7.9 v1(36.969,7.49) ; v1(38.767,30.636) 40.264,30.636 41.4,29.5 v1(41.4,25.4)
  Bottom Layer w0.2: v1(36.969,7.49) 37.952,8.473 37.952,13.523 37.6,13.875 37.6,20.3 38.4,21.1 38.4,22.7 40.2,24.5 40.9,24.5 SB136.1@41.1,24.3 ; v1(38.767,30.636) SB121.1@39.867,30.636 ; 41.4,24.8 v1(41.4,25.4)
PA5: CN7.10 CN12.11 SB120.1 U8.40 | length 62.8
  Top Layer w0.2: v1(28.7,14.1) 28.7,9.3 30.01,7.99 U8.40@34.842,7.99 U8.40@35.042,7.99 ; v1(28.9,22.9) v1(28.9,24.7) ; CN7.10@48.26,34.544 50.056,34.544 51.605,32.995 CN12.11@53.34,32.995
  Signal Layer 2 w0.2: v1(33.1,29.1) 35.2,29.1 41.959,35.859 46.945,35.859 CN7.10@48.26,34.544
  Bottom Layer w0.2: v1(28.7,14.1) 28.7,20 29.052,20.352 29.052,20.787 28.9,20.939 v1(28.9,22.9) ; v1(28.9,24.7) 28.9,25.473 30.967,27.54 31.779,27.54 32.1,27.861 32.1,28.1 v1(33.1,29.1) ; SB120.1@40.867,32.036 41.13,32.3 41.744,32.3 45.244,35.8 47.004,35.8 CN7.10@48.26,34.544
PA6: CN7.12 CN12.13 U8.41 | length 50.2
  Top Layer w0.2: v1(29.3,14.5) 29.3,9.4 30.21,8.49 U8.41@34.842,8.49 U8.41@35.042,8.49 ; v1(29.5,22.3) v1(29.5,24.6) ; v1(33.1,28.1) 34.2,28.1 35.9,29.8 40.739,29.8 44.239,33.3 46.964,33.3 CN7.12@48.26,32.004 50.296,32.004 51.845,30.455 CN12.13@53.34,30.455
  Bottom Layer w0.2: v1(29.3,14.5) 29.3,20.138 29.5,20.338 v1(29.5,22.3) ; v1(29.5,24.6) 29.5,24.873 31.84,27.213 32.213,27.213 v1(33.1,28.1)
PA7: CN7.14 CN12.15 U8.42 | length 47.3
  Top Layer w0.2: v1(30,15.1) 30,9.6 30.61,8.99 U8.42@34.842,8.99 U8.42@35.042,8.99 ; v1(30.9,22.5) v1(30.9,24.6) ; v1(33.1,27.4) 33.364,27.664 34.5,27.664 35.6,28.764 40.364,28.764 42.3,30.7 47.024,30.7 CN7.14@48.26,29.464 50.136,29.464 51.685,27.915 CN12.15@53.34,27.915
  Bottom Layer w0.2: v1(30,15.1) 29.8,15.3 29.8,19.9 30.9,21 v1(30.9,22.5) ; v1(30.9,24.6) 30.9,25.2 v1(33.1,27.4)
PA8: CN10.31 CN12.23 U8.100 | length 94.3
  Top Layer w0.2: v1(19.467,22.9) U8.100@19.467,25.865 U8.100@19.467,26.065 ; CN10.31@45.72,-20.32 47,-21.6 v1(51.86,-21.6)
  Signal Layer 2 w0.2: v1(19.467,22.9) 27.139,22.9 32.548,17.491 32.548,17.053 33.33,16.271 35.671,16.271 35.921,16.521 40.321,16.521 40.52,16.72 41.08,16.72 41.279,16.521 52.106,16.521 CN12.23@53.34,17.755
  Signal Layer 3 w0.2: v1(51.86,-21.6) 51.86,-9.7 51.4,-9.24 51.4,-8.6 51.8,-8.2 51.8,-2.1 52.65,-1.25 56.85,-1.25 57.2,-0.9 57.2,13.3 56.6,13.9 55.2,13.9 54.655,14.445 54.655,16.44 CN12.23@53.34,17.755
PA9: CN12.21 R105.1 U8.101 | length 70.7
  Top Layer w0.2: U8.101@18.967,26.09 v1(18.967,27.992)
  Signal Layer 2 w0.2: v1(18.967,27.992) 18.967,24.733 20.181,23.519 27.281,23.519 31.8,19 38,19 39.2,17.8 42.9,17.8 44.9,19.8 47.1,19.8 47.57,20.27 47.57,20.295 CN12.21@53.34,20.295
  Bottom Layer w0.2: R105.1@16.1,45.4 16.1,45.15 16.85,44.4 17.6,44.4 18.2,43.8 21.7,43.8 24.18,41.32 24.18,35.48 23.55,34.85 21.45,34.85 18.967,32.367 ; v1(18.967,27.992) 18.967,32.367 ; 19.4,32.8 18.967,32.367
